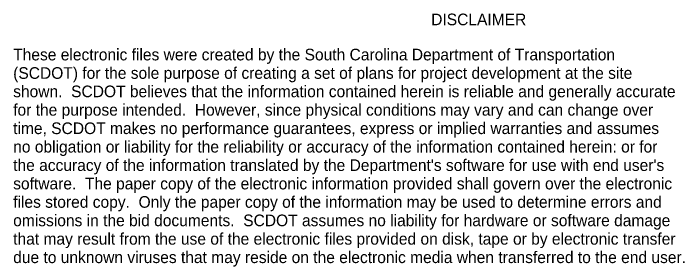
# Model space of a CAD drawing. Extents: x 0 to 36, y 0 to 27.8.
# Drawn here: x 8.75 to 20.73, y 23.32 to 27.84 of the extents above; entities that cross this region are included whole.
import ezdxf

# ---------------------------------------------------------------- set-up
doc = ezdxf.new("R2010")
doc.units = 0
doc.layers.add('BR_USER NOTES', color=7, linetype='Continuous')

msp = doc.modelspace()

# ---------------------------------------------------------------- texts
at = {"layer": 'BR_USER NOTES'}
for s, height, p in [('DISCLAIMER', 0.2077, (16.204, 27.626)), ('These electronic files were created by the South Carolina Department of Transportation', 0.20766, (8.743, 26.999)), ('(SCDOT) for the sole purpose of creating a set of plans for project development at the site', 0.20766, (8.743, 26.67)), ('shown.  SCDOT believes that the information contained herein is reliable and generally accurate', 0.20766, (8.743, 26.342)), ('for the purpose intended.  However, since physical conditions may vary and can change over', 0.20766, (8.743, 26.013)), ('time, SCDOT makes no performance guarantees, express or implied warranties and assumes', 0.20766, (8.743, 25.684)), ('no obligation or liability for the reliability or accuracy of the information contained herein: or for', 0.207659, (8.743, 25.355)), ("the accuracy of the information translated by the Department's software for use with end user's", 0.20766, (8.743, 25.026)), ('software.  The paper copy of the electronic information provided shall govern over the electronic', 0.20766, (8.743, 24.697)), ('files stored copy.  Only the paper copy of the information may be used to determine errors and', 0.20766, (8.743, 24.369)), ('omissions in the bid documents.  SCDOT assumes no liability for hardware or software damage', 0.20766, (8.743, 24.04)), ('that may result from the use of the electronic files provided on disk, tape or by electronic transfer', 0.207659, (8.743, 23.711)), ('due to unknown viruses that may reside on the electronic media when transferred to the end user.', 0.20766, (8.743, 23.382))]:
    msp.add_text(s, height=height, rotation=360, dxfattribs=at).set_placement(p)

doc.saveas('drawing.dxf')
